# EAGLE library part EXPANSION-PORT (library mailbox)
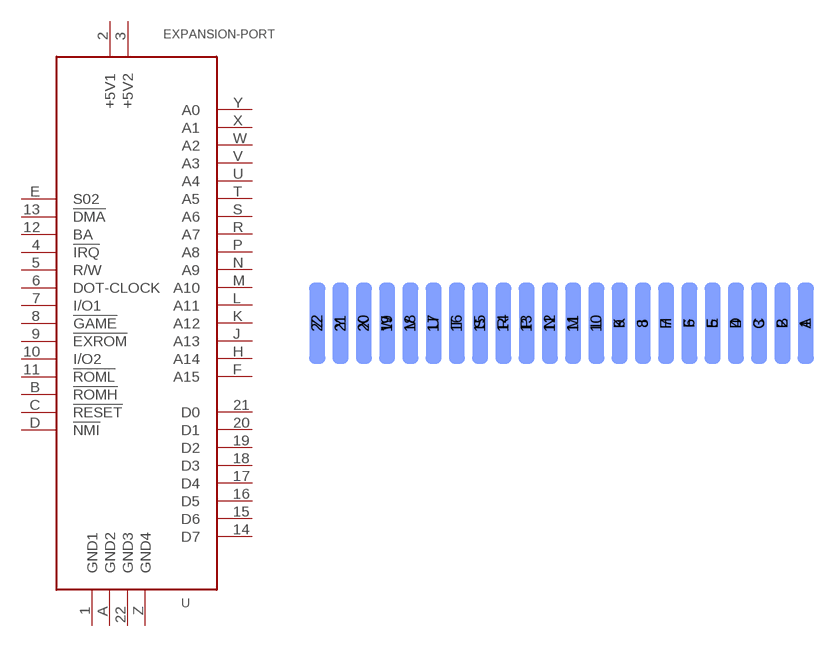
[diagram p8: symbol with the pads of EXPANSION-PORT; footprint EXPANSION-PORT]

Designator prefix -

## EXPANSION-PORT  [EXPANSION-PORT]
1  GND1
2  +5V1
3  +5V2
4  !IRQ
5  R/W
6  DOT-CLOCK
7  I/O1
8  !GAME
9  !EXROM
10  I/O2
11  !ROML
12  BA
13  !DMA
14  D7
15  D6
16  D5
17  D4
18  D3
19  D2
20  D1
21  D0
22  GND3
A  GND2
B  !ROMH
C  !RESET
D  !NMI
E  S02
F  A15
H  A14
J  A13
K  A12
L  A11
M  A10
N  A9
P  A8
R  A7
S  A6
T  A5
U  A4
V  A3
W  A2
X  A1
Y  A0
Z  GND4

## Footprint EXPANSION-PORT (pad centres in mm)
smd 1.778 x 8.89: 1 50.8,0; 2 48.26,0; 3 45.72,0; 4 43.18,0; 5 40.64,0; 6 38.1,0; 7 35.56,0; 8 33.02,0; 9 30.48,0; 10 27.94,0; 11 25.4,0; 12 22.86,0; 13 20.32,0; 14 17.78,0; 15 15.24,0; 16 12.7,0; 17 10.16,0; 18 7.62,0; 19 5.08,0; 20 2.54,0; 21 0,0; 22 -2.54,0
smd 1.778 x 8.89 bottom: A 50.8,0; B 48.26,0; C 45.72,0; D 43.18,0; E 40.64,0; F 38.1,0; H 35.56,0; J 33.02,0; K 30.48,0; L 27.94,0; M 25.4,0; N 22.86,0; P 20.32,0; R 17.78,0; S 15.24,0; T 12.7,0; U 10.16,0; V 7.62,0; W 5.08,0; X 2.54,0; Y 0,0; Z -2.54,0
